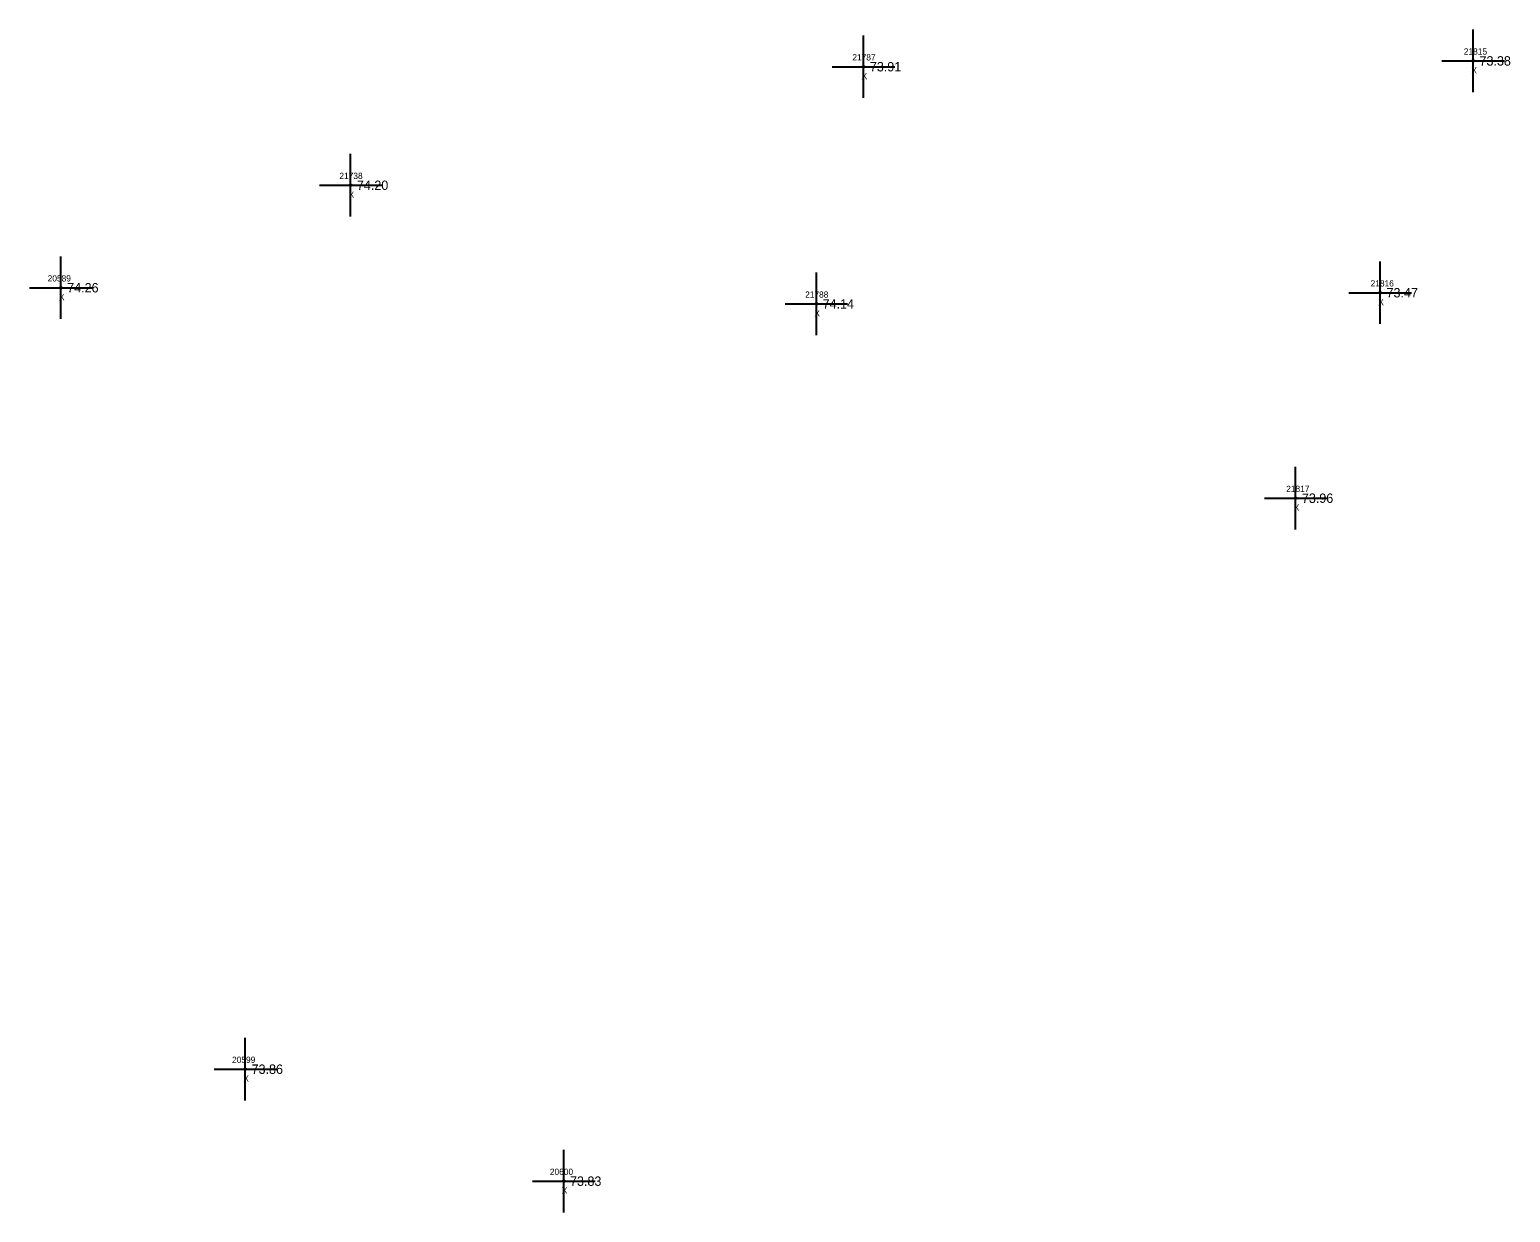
# Model space of a CAD drawing. Extents: x 2140110 to 2141565, y 506241 to 510327.
# Drawn here: x 2140968.9 to 2141205.6, y 508790.1 to 508979.3 of the extents above; entities that cross this region are included whole.
import ezdxf

# ---------------------------------------------------------------- set-up
doc = ezdxf.new("R2010")
doc.units = 0
for name, color, linetype in [('RD_EX_Misc', 7, 'Continuous'), ('RD_EX_Misc_txCode', 7, 'Continuous'), ('RD_EX_TX_Misc_ELEV', 7, 'Continuous'), ('RD_SMD_Locator', 7, 'Continuous')]:
    doc.layers.add(name, color=color, linetype=linetype)

msp = doc.modelspace()

# ---------------------------------------------------------------- linework, layer by layer
at = {"layer": 'RD_EX_Misc'}
for p, q in [((2141199.7, 508969.31), (2141199.7, 508979.31)), ((2141102.23, 508968.38), (2141102.23, 508978.38)), ((2141194.7, 508974.31), (2141204.7, 508974.31)), ((2141097.23, 508973.38), (2141107.23, 508973.38)), ((2141020.22, 508949.42), (2141020.22, 508959.42)), ((2141015.22, 508954.42), (2141025.22, 508954.42)), ((2140973.9, 508933.03), (2140973.9, 508943.03)), ((2141184.83, 508932.23), (2141184.83, 508942.23)), ((2141094.68, 508930.44), (2141094.68, 508940.44)), ((2140968.9, 508938.03), (2140978.9, 508938.03)), ((2141179.83, 508937.23), (2141189.83, 508937.23)), ((2141089.68, 508935.44), (2141099.68, 508935.44)), ((2141171.3, 508899.37), (2141171.3, 508909.37)), ((2141166.3, 508904.37), (2141176.3, 508904.37)), ((2141003.38, 508808.05), (2141003.38, 508818.05)), ((2140998.38, 508813.05), (2141008.38, 508813.05)), ((2141054.29, 508790.14), (2141054.29, 508800.14)), ((2141049.29, 508795.14), (2141059.29, 508795.14))]:
    msp.add_line(p, q, dxfattribs=at)
at = {"layer": 'RD_SMD_Locator'}
for centre in [(2141199.7, 508974.31), (2141102.23, 508973.38), (2141020.22, 508954.42), (2140973.9, 508938.03), (2141184.83, 508937.23), (2141094.68, 508935.44), (2141171.3, 508904.37), (2141003.38, 508813.05), (2141054.29, 508795.14)]:
    msp.add_circle(centre, 0.15, dxfattribs=at)

# ---------------------------------------------------------------- texts
at = {"layer": 'RD_EX_Misc_txCode'}
for s, p in [('21787', (2141100.43, 508974.38)), ('21815', (2141198.19, 508975.31)), ('X', (2141101.91, 508971.38)), ('X', (2141199.39, 508972.31)), ('21738', (2141018.42, 508955.42)), ('X', (2141019.9, 508952.42)), ('20589', (2140971.78, 508939.03)), ('21816', (2141183.29, 508938.23)), ('X', (2140973.58, 508936.03)), ('21788', (2141092.88, 508936.44)), ('X', (2141184.51, 508935.23)), ('X', (2141094.36, 508933.44)), ('21817', (2141169.79, 508905.37)), ('X', (2141170.99, 508902.37)), ('20599', (2141001.26, 508814.05)), ('X', (2141003.06, 508811.05)), ('20600', (2141052.07, 508796.14)), ('X', (2141053.97, 508793.14))]:
    msp.add_text(s, height=1, dxfattribs=at).set_placement(p)
at = {"layer": 'RD_EX_TX_Misc_ELEV'}
for s, p in [('73.91', (2141103.23, 508972.63)), ('73.38', (2141200.7, 508973.56)), ('74.20', (2141021.22, 508953.67)), ('74.26', (2140974.9, 508937.28)), ('73.47', (2141185.83, 508936.48)), ('74.14', (2141095.68, 508934.69)), ('73.96', (2141172.3, 508903.62)), ('73.86', (2141004.38, 508812.3)), ('73.83', (2141055.29, 508794.39))]:
    msp.add_text(s, height=1.5, dxfattribs=at).set_placement(p)

doc.saveas('drawing.dxf')
